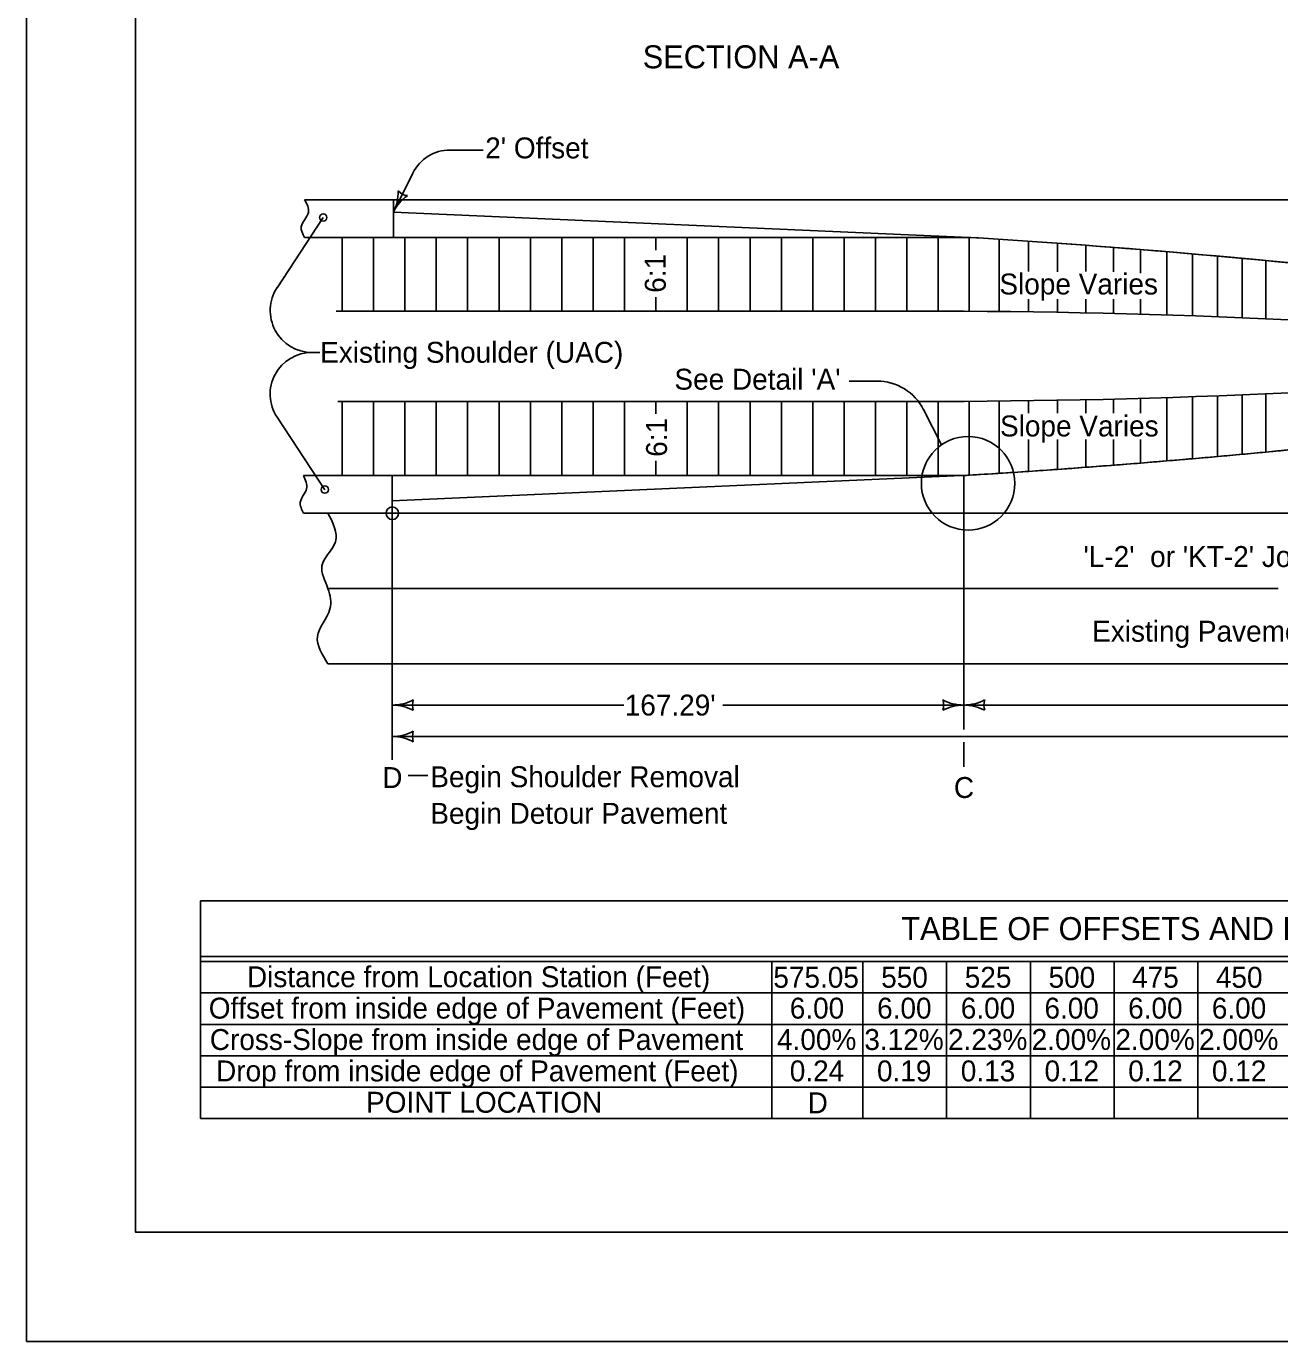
# Model space of a CAD drawing. Extents: x -2135039 to -2131695, y -2139150 to -2136566.
# Drawn here: x -2135039 to -2133841, y -2139150 to -2137893 of the extents above; entities that cross this region are included whole.
import ezdxf

# ---------------------------------------------------------------- set-up
doc = ezdxf.new("R2010")
doc.units = 0
for name, color, linetype in [('dsnDOTLogo', 7, 'Continuous'), ('dsnStdDimension', 7, 'Continuous'), ('dsnStdLineDrawingWt4', 7, 'Continuous'), ('dsnStdShading', 7, 'Continuous'), ('Level 1', 7, 'Continuous'), ('Level 11', 7, 'Continuous'), ('Level 2', 7, 'Continuous'), ('Level 3', 7, 'Continuous'), ('Level 6', 7, 'Continuous'), ('Level 7', 7, 'Continuous'), ('Level 9', 7, 'Continuous')]:
    doc.layers.add(name, color=color, linetype=linetype)

msp = doc.modelspace()

# ---------------------------------------------------------------- linework, layer by layer
at = {"layer": 'dsnDOTLogo'}
msp.add_lwpolyline([(-2135038.9, -2139150.4), (-2131694.9, -2139150.4), (-2131694.9, -2136566.4), (-2135038.9, -2136566.4)], close=True, dxfattribs=at)
at = {"layer": 'dsnStdDimension'}
for p, q in [((-2134602.1, -2138011.3), (-2134633.7, -2138011.3)), ((-2134669.5, -2138033.4), (-2134688, -2138070.6)), ((-2134799.1, -2138142.9), (-2134755, -2138075.8)), ((-2134758.2, -2138204.8), (-2134765.8, -2138204.8)), ((-2134225.6, -2138232.2), (-2134252.2, -2138232.2)), ((-2134753.6, -2138336.2), (-2134799.2, -2138266.8)), ((-2134163.9, -2138293.2), (-2134181, -2138259.5)), ((-2134142.7, -2138322.5), (-2134142.7, -2138565.3)), ((-2134689, -2138358.5), (-2134689, -2138594.1)), ((-2134689, -2138541.9), (-2134467.8, -2138541.9)), ((-2134373.1, -2138541.9), (-2134142.7, -2138541.9)), ((-2134142.7, -2138541.9), (-2133727.6, -2138541.9)), ((-2134689, -2138571.9), (-2133779.7, -2138571.9)), ((-2134142.7, -2138601), (-2134142.7, -2138577.4)), ((-2134674, -2138609.1), (-2134655.1, -2138609.1))]:
    msp.add_line(p, q, dxfattribs=at)
for centre, radius in [((-2134755, -2138075.8), 3.5), ((-2134138.5, -2138329.9), 44.7), ((-2134753.6, -2138335.9), 3.5), ((-2134689, -2138358.5), 6)]:
    msp.add_circle(centre, radius, dxfattribs=at)
for centre, radius, start, end in [((-2134633.7, -2138051.3), 40, 90, 153.446), ((-2134726, -2138051.6), 42.5, 333.446, 1.5185), ((-2134650, -2138089.6), 42.5, 125.3735, 153.446), ((-2134672.1, -2138038.7), 16.4, 225.7126, 261.1793), ((-2134765.7, -2138164.8), 40, 146.6736, 270), ((-2134765.8, -2138244.8), 40, 90, 213.2786), ((-2134225.6, -2138282.2), 50, 26.9846, 90), ((-2134689, -2138499.4), 42.5, 270, 298.0725), ((-2134689, -2138584.4), 42.5, 61.9275, 90), ((-2134653.3, -2138541.9), 16.4, 162.2666, 197.7334), ((-2134178.3, -2138541.9), 16.4, 342.2666, 17.7333), ((-2134142.7, -2138499.4), 42.5, 241.9275, 270), ((-2134142.7, -2138584.4), 42.5, 90, 118.0725), ((-2134142.7, -2138499.4), 42.5, 270, 298.0725), ((-2134142.7, -2138584.4), 42.5, 61.9275, 90), ((-2134107, -2138541.9), 16.4, 162.2666, 197.7334), ((-2134689, -2138529.4), 42.5, 270, 298.0725), ((-2134653.3, -2138571.9), 16.4, 162.2666, 197.7334), ((-2134689, -2138614.4), 42.5, 61.9275, 90)]:
    msp.add_arc(centre, radius, start, end, dxfattribs=at)
at = {"layer": 'dsnStdLineDrawingWt4'}
for p, q in [((-2134772.9, -2138058.8), (-2134688, -2138058.8)), ((-2134688, -2138094.8), (-2134688, -2138058.8)), ((-2134688, -2138094.8), (-2134688, -2138058.8)), ((-2134688, -2138058.8), (-2133150.7, -2138058.8)), ((-2134772.9, -2138094.8), (-2134688, -2138094.8)), ((-2134737, -2138095.2), (-2134737, -2138165.3)), ((-2134707, -2138095.2), (-2134707, -2138165.3)), ((-2134688, -2138094.8), (-2134137.6, -2138094.8)), ((-2134677, -2138095.2), (-2134677, -2138165.3)), ((-2134647, -2138095.2), (-2134647, -2138165.3)), ((-2134617, -2138095.2), (-2134617, -2138165.3)), ((-2134587, -2138095.2), (-2134587, -2138165.3)), ((-2134557, -2138095.2), (-2134557, -2138165.3)), ((-2134527, -2138095.2), (-2134527, -2138165.3)), ((-2134497, -2138095.2), (-2134497, -2138165.3)), ((-2134467, -2138095.2), (-2134467, -2138165.3)), ((-2134437, -2138095.2), (-2134437, -2138107.2)), ((-2134407, -2138095.2), (-2134407, -2138165.3)), ((-2134377, -2138095.2), (-2134377, -2138165.3)), ((-2134347, -2138095.2), (-2134347, -2138165.3)), ((-2134317, -2138095.2), (-2134317, -2138165.3)), ((-2134287, -2138095.2), (-2134287, -2138165.3)), ((-2134257, -2138094.5), (-2134257, -2138165.3)), ((-2134227, -2138094.5), (-2134227, -2138165.3)), ((-2134197, -2138094.5), (-2134197, -2138165.3)), ((-2134167, -2138094.5), (-2134167, -2138165.3)), ((-2134137.6, -2138094.8), (-2134137.6, -2138165.3)), ((-2134108.8, -2138096.6), (-2134108.8, -2138165.3)), ((-2134080.6, -2138098.5), (-2134080.6, -2138127.4)), ((-2134053, -2138100.4), (-2134053, -2138127.6)), ((-2134026, -2138102.4), (-2134026, -2138127.4)), ((-2133999.6, -2138104.4), (-2133999.6, -2138127.8)), ((-2133973.8, -2138106.4), (-2133973.8, -2138129)), ((-2133948.6, -2138108.5), (-2133948.6, -2138169)), ((-2133924, -2138110.6), (-2133924, -2138169.8)), ((-2133900, -2138112.7), (-2133900, -2138170.7)), ((-2133876.6, -2138114.8), (-2133876.6, -2138171.6)), ((-2133853.8, -2138116.9), (-2133853.8, -2138172.6)), ((-2134437, -2138152.1), (-2134437, -2138165.3)), ((-2134080.6, -2138166), (-2134080.6, -2138154)), ((-2134053, -2138166.5), (-2134053, -2138154)), ((-2134026, -2138167), (-2134026, -2138154)), ((-2133999.6, -2138167.6), (-2133999.6, -2138154)), ((-2133973.8, -2138168.3), (-2133973.8, -2138154)), ((-2134742.7, -2138165.3), (-2134186.7, -2138165.3)), ((-2133853.8, -2138300.1), (-2133853.8, -2138244.4)), ((-2134741, -2138251.7), (-2134186.7, -2138251.7)), ((-2134737, -2138322.2), (-2134737, -2138251.7)), ((-2134707, -2138322.2), (-2134707, -2138251.7)), ((-2134677, -2138322.2), (-2134677, -2138251.7)), ((-2134647, -2138322.2), (-2134647, -2138251.7)), ((-2134617, -2138322.2), (-2134617, -2138251.7)), ((-2134587, -2138322.2), (-2134587, -2138251.7)), ((-2134557, -2138322.2), (-2134557, -2138251.7)), ((-2134527, -2138322.2), (-2134527, -2138251.7)), ((-2134497, -2138322.2), (-2134497, -2138251.7)), ((-2134467, -2138322.2), (-2134467, -2138251.7)), ((-2134437, -2138263.5), (-2134437, -2138251.7)), ((-2134407, -2138322.2), (-2134407, -2138251.7)), ((-2134377, -2138322.2), (-2134377, -2138251.7)), ((-2134347, -2138322.2), (-2134347, -2138251.7)), ((-2134317, -2138322.2), (-2134317, -2138251.7)), ((-2134287, -2138322.2), (-2134287, -2138251.7)), ((-2134257, -2138322.2), (-2134257, -2138251.7)), ((-2134227, -2138322.2), (-2134227, -2138251.7)), ((-2134197, -2138323), (-2134197, -2138251.7)), ((-2134167, -2138321.4), (-2134167, -2138251.7)), ((-2134137.6, -2138322.2), (-2134137.6, -2138251.7)), ((-2134108.8, -2138320.4), (-2134108.8, -2138251.7)), ((-2134080.6, -2138263), (-2134080.6, -2138251)), ((-2134053, -2138263), (-2134053, -2138250.5)), ((-2134026, -2138263), (-2134026, -2138250)), ((-2133999.6, -2138263), (-2133999.6, -2138249.4)), ((-2133973.8, -2138263), (-2133973.8, -2138248.7)), ((-2133948.6, -2138308.5), (-2133948.6, -2138248)), ((-2133924, -2138306.4), (-2133924, -2138247.2)), ((-2133900, -2138304.3), (-2133900, -2138246.3)), ((-2133876.6, -2138302.2), (-2133876.6, -2138245.4)), ((-2134080.6, -2138318.5), (-2134080.6, -2138288)), ((-2134053, -2138316.6), (-2134053, -2138288)), ((-2134026, -2138314.6), (-2134026, -2138288)), ((-2133999.6, -2138312.6), (-2133999.6, -2138288)), ((-2133973.8, -2138310.6), (-2133973.8, -2138288)), ((-2134437, -2138322.2), (-2134437, -2138308.5)), ((-2134773.9, -2138322.5), (-2134689, -2138322.5)), ((-2134689, -2138358.5), (-2134689, -2138322.5)), ((-2134689, -2138322.5), (-2134142.7, -2138322.5)), ((-2134333.5, -2138322.5), (-2134186.7, -2138322.5)), ((-2134773.9, -2138358.5), (-2134689, -2138358.5)), ((-2134689, -2138358.5), (-2133150.7, -2138358.5)), ((-2134750.5, -2138502.5), (-2132911.4, -2138502.5))]:
    msp.add_line(p, q, dxfattribs=at)
for centre, radius, start, end in [((-2134663.9, -2146675.7), 8597, 80.50385, 86.52493), ((-2134186.7, -2145798.6), 7633.3, 84.67428, 90), ((-2134186.7, -2130618.4), 7633.3, 270, 275.32661), ((-2134663.8, -2129742.7), 8595.6, 273.47608, 279.49716)]:
    msp.add_arc(centre, radius, start, end, dxfattribs=at)
for points in [[(-2134772.9, -2138058.8), (-2134769.2, -2138071), (-2134776.1, -2138084.7), (-2134772.9, -2138094.8)], [(-2134773.9, -2138322.5), (-2134771, -2138335.2), (-2134777, -2138348), (-2134773.9, -2138358.5)], [(-2134750.5, -2138358.5), (-2134743.4, -2138385.7), (-2134756.3, -2138408.8), (-2134750.5, -2138430.5), (-2134748.6, -2138449.9), (-2134760.6, -2138476.4), (-2134750.5, -2138502.5)]]:
    msp.add_spline(points, degree=3, dxfattribs=at)
at = {"layer": 'dsnStdShading'}
for p, q in [((-2133150.7, -2138058.8), (-2134688, -2138058.8)), ((-2134688, -2138058.8), (-2134688, -2138094.8)), ((-2133924, -2138306.4), (-2133924, -2138306.4)), ((-2133900, -2138304.3), (-2133900, -2138304.3)), ((-2133876.6, -2138302.2), (-2133876.6, -2138302.2)), ((-2133853.8, -2138300.1), (-2133853.8, -2138300.1)), ((-2134080.6, -2138318.5), (-2134080.6, -2138318.5)), ((-2134053, -2138316.6), (-2134053, -2138316.6)), ((-2134026, -2138314.6), (-2134026, -2138314.6)), ((-2133999.6, -2138312.6), (-2133999.6, -2138312.6)), ((-2133973.8, -2138310.6), (-2133973.8, -2138310.6)), ((-2133948.6, -2138308.5), (-2133948.6, -2138308.5)), ((-2134333.5, -2138322.5), (-2134689, -2138322.5)), ((-2134689, -2138322.5), (-2134689, -2138358.5)), ((-2134142.7, -2138322.5), (-2134186.7, -2138322.5)), ((-2134137.6, -2138322.2), (-2134137.6, -2138322.2)), ((-2134108.8, -2138320.4), (-2134108.8, -2138320.4)), ((-2134689, -2138358.5), (-2133150.7, -2138358.5))]:
    msp.add_line(p, q, dxfattribs=at)
for points in [[(-2134688, -2138094.8), (-2134257, -2138094.8), (-2134227, -2138094.8), (-2134197, -2138094.8), (-2134167, -2138094.8), (-2134137.6, -2138094.8)], [(-2134137.6, -2138094.8), (-2134137.6, -2138094.8)], [(-2133924, -2138306.4), (-2133924, -2138306.4)], [(-2133900, -2138304.3), (-2133900, -2138304.3)], [(-2133876.6, -2138302.2), (-2133876.6, -2138302.2)], [(-2133853.8, -2138300.1), (-2133853.8, -2138300.1)], [(-2134080.6, -2138318.5), (-2134080.6, -2138318.5)], [(-2134053, -2138316.6), (-2134053, -2138316.6)], [(-2134026, -2138314.6), (-2134026, -2138314.6)], [(-2133999.6, -2138312.6), (-2133999.6, -2138312.6)], [(-2133973.8, -2138310.6), (-2133973.8, -2138310.6)], [(-2133948.6, -2138308.5), (-2133948.6, -2138308.5)], [(-2134186.7, -2138322.5), (-2134197, -2138322.5), (-2134333.5, -2138322.5)], [(-2134333.5, -2138322.5), (-2134333.5, -2138322.5)], [(-2134186.7, -2138322.5), (-2134186.7, -2138322.5)], [(-2134137.6, -2138322.2), (-2134137.6, -2138322.2)], [(-2134108.8, -2138320.4), (-2134108.8, -2138320.4)]]:
    msp.add_lwpolyline(points, dxfattribs=at)
for centre, radius, start, end in [((-2134663.9, -2146675.7), 8597, 83.51664, 86.48991), ((-2134663.8, -2129742.7), 8595.6, 274.77331, 274.93787), ((-2134663.8, -2129742.7), 8595.6, 274.93787, 275.09846), ((-2134663.8, -2129742.7), 8595.6, 275.09846, 275.25508), ((-2134663.8, -2129742.7), 8595.6, 275.25508, 275.40772), ((-2134663.8, -2129742.7), 8595.6, 275.40772, 275.55638), ((-2134663.8, -2129742.7), 8595.6, 273.70252, 273.89091), ((-2134663.8, -2129742.7), 8595.6, 273.89091, 274.07532), ((-2134663.8, -2129742.7), 8595.6, 274.07532, 274.25577), ((-2134663.8, -2129742.7), 8595.6, 274.25578, 274.43226), ((-2134663.8, -2129742.7), 8595.6, 274.43226, 274.60477), ((-2134663.8, -2129742.7), 8595.6, 274.60477, 274.77331), ((-2134663.8, -2129742.7), 8595.6, 273.47608, 273.51017), ((-2134663.8, -2129742.7), 8595.6, 273.51017, 273.70252)]:
    msp.add_arc(centre, radius, start, end, dxfattribs=at)
at = {"layer": 'Level 1'}
msp.add_lwpolyline([(-2134934.4, -2137035.9), (-2131799.4, -2137035.9), (-2131799.4, -2139045.9), (-2134934.4, -2139045.9)], close=True, dxfattribs=at)
at = {"layer": 'Level 11'}
for p, q in [((-2134872.5, -2138729.1), (-2132710.1, -2138729.1)), ((-2134872.5, -2138729.1), (-2134872.5, -2138937.1)), ((-2134872.5, -2138937.1), (-2132710.1, -2138937.1))]:
    msp.add_line(p, q, dxfattribs=at)
at = {"layer": 'Level 2'}
for p, q in [((-2134872.5, -2138782.1), (-2132710.1, -2138782.1)), ((-2134872.5, -2138787.1), (-2132710.1, -2138787.1)), ((-2134326, -2138787.1), (-2134326, -2138937.1)), ((-2134239, -2138787.1), (-2134239, -2138937.1)), ((-2134159, -2138787.1), (-2134159, -2138937.1)), ((-2134079, -2138787.1), (-2134079, -2138937.1)), ((-2133999, -2138787.1), (-2133999, -2138937.1)), ((-2133919, -2138787.1), (-2133919, -2138937.1))]:
    msp.add_line(p, q, dxfattribs=at)
at = {"layer": 'Level 3'}
for p, q in [((-2134137.6, -2138094.8), (-2134688, -2138070.6)), ((-2134137.6, -2138322.2), (-2134689, -2138346.5)), ((-2134750.5, -2138430.5), (-2133842.2, -2138430.5))]:
    msp.add_line(p, q, dxfattribs=at)
at = {"layer": 'Level 9'}
for p, q in [((-2134872.5, -2138817.1), (-2132710.1, -2138817.1)), ((-2134872.5, -2138847.1), (-2132710.1, -2138847.1)), ((-2134872.5, -2138877.1), (-2132710.1, -2138877.1)), ((-2134872.5, -2138907.1), (-2132710.1, -2138907.1))]:
    msp.add_line(p, q, dxfattribs=at)

# ---------------------------------------------------------------- texts
at = {"layer": 'Level 6'}
for s, p in [('SECTION A-A', (-2134449.6, -2137933.2)), ('TABLE OF OFFSETS AND DROPS (PAVED SHOULDERS)', (-2134202.4, -2138766.6))]:
    msp.add_text(s, height=22, dxfattribs=at).set_placement(p)
at = {"layer": 'Level 7'}
for s, p in [("2' Offset", (-2134600.2, -2138019.3)), ('Slope Varies', (-2134108.6, -2138149.4)), ('Existing Shoulder (UAC)', (-2134758, -2138214.7)), ("See Detail 'A'", (-2134419.3, -2138240.4)), ('Slope Varies', (-2134108, -2138285.1)), ("'L-2'  or 'KT-2' Joint", (-2134028.2, -2138409.9)), ('Existing Pavement', (-2134019.9, -2138481.3)), ("167.29'", (-2134466.8, -2138551.9)), ('D', (-2134698.6, -2138621.2)), ('Begin Shoulder Removal', (-2134652.7, -2138620.4)), ('C', (-2134152.1, -2138630.7)), ('Begin Detour Pavement', (-2134652.7, -2138655.4)), ('Distance from Location Station (Feet)', (-2134828, -2138811.6)), ('575.05', (-2134324.7, -2138812.1)), ('550', (-2134221.6, -2138812.1)), ('525', (-2134141.7, -2138812.1)), ('500', (-2134061.6, -2138812.1)), ('475', (-2133981.7, -2138812.1)), ('450', (-2133901.6, -2138812.1)), ('Offset from inside edge of Pavement (Feet)', (-2134864.5, -2138841.6)), ('6.00', (-2134309, -2138841.6)), ('6.00', (-2134225.5, -2138841.6)), ('6.00', (-2134145.5, -2138841.6)), ('6.00', (-2134065.5, -2138841.6)), ('6.00', (-2133985.5, -2138841.6)), ('6.00', (-2133905.5, -2138841.6)), ('Cross-Slope from inside edge of Pavement', (-2134863.5, -2138871.6)), ('4.00%', (-2134321.2, -2138871.6)), ('3.12%', (-2134237.7, -2138871.6)), ('2.23%', (-2134157.7, -2138871.6)), ('2.00%', (-2134077.7, -2138871.6)), ('2.00%', (-2133997.7, -2138871.6)), ('2.00%', (-2133917.7, -2138871.6)), ('Drop from inside edge of Pavement (Feet)', (-2134857.5, -2138901.6)), ('0.24', (-2134309, -2138901.6)), ('0.19', (-2134225.6, -2138901.6)), ('0.13', (-2134145.5, -2138901.6)), ('0.12', (-2134065.4, -2138901.6)), ('0.12', (-2133985.4, -2138901.6)), ('0.12', (-2133905.4, -2138901.6)), ('POINT LOCATION', (-2134714.1, -2138931.6)), ('D', (-2134291.9, -2138932.1))]:
    msp.add_text(s, height=20, dxfattribs=at).set_placement(p)
for p in [(-2134427.6, -2138147.8), (-2134426.4, -2138304.6)]:
    msp.add_text('6:1', height=20, rotation=90, dxfattribs=at).set_placement(p)

doc.saveas('drawing.dxf')
